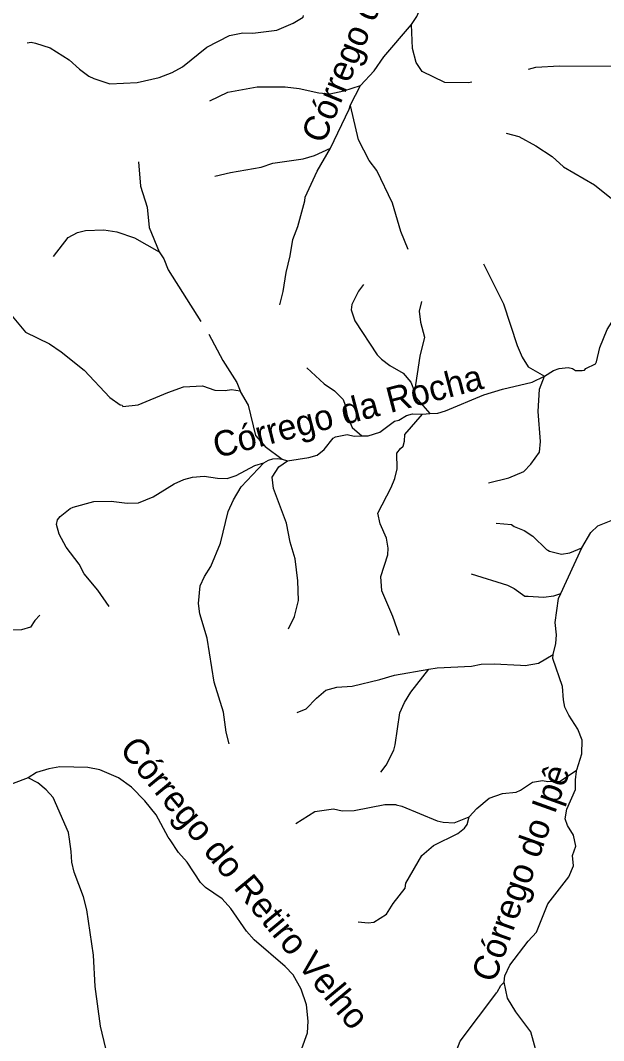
# Model space of a CAD drawing. Extents: x 393 to 446.6, y 8175.5 to 8231.
# Drawn here: x 437.39 to 441.07, y 8195.85 to 8202.28 of the extents above; entities that cross this region are included whole.
import ezdxf
from ezdxf.enums import TextEntityAlignment as Align

# ---------------------------------------------------------------- set-up
doc = ezdxf.new("R2010")
doc.units = 0
doc.header["$LTSCALE"] = 0.064
doc.linetypes.add('LONG_DASHED', pattern=[7.5, 6, -1.5])
doc.layers.add('61', color=7, linetype='Continuous')
doc.layers.add('7', color=7, linetype='Continuous', lineweight=25)
doc.layers.add('9', color=7, linetype='LONG_DASHED', lineweight=25)

msp = doc.modelspace()

# ---------------------------------------------------------------- linework, layer by layer
at = {"layer": '7'}
msp.add_lwpolyline([(440.601, 8201.9686), (440.6453, 8201.9814), (440.7959, 8201.9908), (441.1931, 8201.9875), (441.2706, 8201.9972), (441.3352, 8201.9908), (441.4224, 8201.9682), (441.4773, 8201.9536), (441.6582, 8201.881), (441.7421, 8201.8616), (441.8293, 8201.8616), (441.9424, 8201.8842), (442.0425, 8201.8955), (442.0828, 8201.8858), (442.0958, 8201.8745), (442.1168, 8201.8616), (442.1523, 8201.8551), (442.1878, 8201.8584), (442.2427, 8201.8761), (442.3235, 8201.9181), (442.3692, 8201.9452)], dxfattribs=at)
at = {"layer": '9'}
for p, q in [((439.9319, 8199.7953), (439.9768, 8199.7989)), ((439.0454, 8199.5117), (439.08, 8199.5009)), ((440.8033, 8198.6634), (440.9364, 8198.9526))]:
    msp.add_line(p, q, dxfattribs=at)
for points in [[(439.8622, 8202.2497), (439.8959, 8202.3014), (439.9141, 8202.3443), (439.9338, 8202.4352)], [(437.4373, 8202.1354), (437.4625, 8202.1389), (437.4894, 8202.1331), (437.5824, 8202.1038), (437.7019, 8202.0279), (437.7665, 8201.9698), (437.8262, 8201.9246), (437.8569, 8201.91), (437.9587, 8201.8762), (438.1315, 8201.8842), (438.2703, 8201.9165), (438.3527, 8201.9472), (438.4173, 8201.9827), (438.5707, 8202.107), (438.7144, 8202.1813), (438.7968, 8202.1975), (438.8597, 8202.1959), (439.0131, 8202.2152), (439.1149, 8202.2588), (439.1778, 8202.2976), (439.1804, 8202.3066)], [(439.5405, 8201.8656), (439.6254, 8201.9574), (439.6864, 8202.0472), (439.8622, 8202.2497)], [(440.2431, 8201.8865), (440.2213, 8201.8818), (440.0712, 8201.8859), (439.9287, 8201.954), (439.8919, 8202.0111), (439.8672, 8202.0982), (439.8622, 8202.2497)], [(438.5897, 8201.7686), (438.702, 8201.8234), (438.8885, 8201.8569), (439.064, 8201.8583), (439.1525, 8201.8464), (439.2766, 8201.8198), (439.3471, 8201.8139), (439.4348, 8201.8327), (439.5405, 8201.8656)], [(439.3506, 8201.4716), (439.4679, 8201.7171), (439.4759, 8201.7432), (439.5405, 8201.8656)], [(439.8417, 8200.8328), (439.7941, 8200.9464), (439.7421, 8201.1238), (439.642, 8201.33), (439.5951, 8201.3937), (439.5274, 8201.5227), (439.4765, 8201.7408), (439.4759, 8201.7432)], [(440.4592, 8201.5652), (440.5387, 8201.544), (440.647, 8201.4861), (440.7492, 8201.4188), (440.8209, 8201.3524), (441.0164, 8201.24), (441.1228, 8201.1534), (441.1525, 8201.1188), (441.195, 8201.043), (441.2443, 8200.8713), (441.2933, 8200.7752), (441.3225, 8200.7432), (441.3971, 8200.6977)], [(438.6202, 8201.2939), (438.7205, 8201.3176), (438.9133, 8201.3503), (438.9866, 8201.3767), (439.1791, 8201.4033), (439.2505, 8201.4241), (439.3506, 8201.4716)], [(439.03, 8200.4826), (439.053, 8200.5677), (439.0701, 8200.6874), (439.0968, 8200.7935), (439.1132, 8200.8953), (439.1437, 8200.9782), (439.1891, 8201.1398), (439.1908, 8201.1631), (439.2657, 8201.3252), (439.3506, 8201.4716)], [(438.1402, 8201.3847), (438.1509, 8201.2316), (438.1948, 8201.0989), (438.2056, 8200.9708), (438.2699, 8200.8168)], [(437.604, 8200.7874), (437.6954, 8200.9087), (437.7545, 8200.9395), (437.8049, 8200.9522), (437.9216, 8200.9556), (438.002, 8200.9438), (438.1148, 8200.9062), (438.2699, 8200.8168)], [(438.2699, 8200.8168), (438.2982, 8200.7744), (438.3273, 8200.7045), (438.5822, 8200.2995), (438.6708, 8200.1332), (438.7592, 8199.9939), (438.7802, 8199.9408)], [(440.3154, 8200.7411), (440.4421, 8200.4907), (440.5275, 8200.2264), (440.5601, 8200.1531), (440.5983, 8200.0926), (440.6999, 8200.0351)], [(440.6999, 8200.0351), (440.7587, 8200.0692), (440.7942, 8200.0821), (440.8508, 8200.0885), (440.8766, 8200.0821), (440.896, 8200.0692), (440.938, 8200.0692), (440.9541, 8200.0724), (440.9622, 8200.0821), (441.0219, 8200.1111), (441.03, 8200.1241), (441.051, 8200.2145), (441.0962, 8200.3292), (441.1253, 8200.3744), (441.1737, 8200.4196), (441.319, 8200.5181), (441.3416, 8200.5552), (441.3449, 8200.6053), (441.361, 8200.6699), (441.3971, 8200.6977)], [(439.5596, 8200.6119), (439.5265, 8200.5702), (439.4861, 8200.4867), (439.4817, 8200.4526), (439.5049, 8200.3836), (439.6455, 8200.1688), (439.6716, 8200.1405), (439.725, 8200.1011), (439.8082, 8200.0523), (439.8585, 8199.997), (439.88, 8199.9383), (439.88, 8199.9382)], [(437.2906, 8200.4762), (437.4256, 8200.3117), (437.5785, 8200.2372), (437.6521, 8200.188), (437.7955, 8200.0723), (437.9578, 8199.8989), (438.0244, 8199.8533), (438.0359, 8199.8522), (438.0414, 8199.8435), (438.1371, 8199.8525), (438.3252, 8199.9318), (438.4226, 8199.9659), (438.5433, 8199.9722), (438.6215, 8199.9449), (438.6859, 8199.9432), (438.7266, 8199.9497), (438.7802, 8199.9408)], [(439.9259, 8200.5041), (439.911, 8200.4428), (439.9185, 8200.3753), (439.9445, 8200.279), (439.9147, 8200.161), (439.88, 8199.9382)], [(439.2007, 8200.0875), (439.3113, 8199.9856), (439.3769, 8199.9424), (439.431, 8199.8866), (439.4439, 8199.8517), (439.4559, 8199.7842), (439.4883, 8199.7105), (439.5484, 8199.6577)], [(439.9768, 8199.7989), (440.0287, 8199.801), (440.0757, 8199.8156), (440.3179, 8199.9174), (440.4358, 8199.9529), (440.6231, 8199.9965), (440.6999, 8200.0351)], [(440.3471, 8199.3614), (440.4752, 8199.3929), (440.5696, 8199.4329), (440.6157, 8199.4803), (440.6688, 8199.5555), (440.6763, 8199.6213), (440.6602, 8199.8118), (440.6701, 8199.9518), (440.6999, 8200.0351)], [(438.7802, 8199.9408), (438.7814, 8199.9378), (438.8304, 8199.852), (438.8783, 8199.6609), (438.9379, 8199.5906), (439.0454, 8199.5117)], [(439.88, 8199.9382), (439.8797, 8199.9361), (439.8898, 8199.899), (439.9768, 8199.7989)], [(439.5484, 8199.6577), (439.5891, 8199.6581), (439.6616, 8199.6815), (439.7543, 8199.7494), (439.7808, 8199.7562), (439.8302, 8199.7866), (439.869, 8199.7963), (439.9319, 8199.7953)], [(439.7865, 8198.3993), (439.7445, 8198.5191), (439.6752, 8198.6806), (439.6688, 8198.7717), (439.7122, 8198.9088), (439.7138, 8198.9501), (439.7041, 8199.0131), (439.665, 8199.1031), (439.6497, 8199.1714), (439.7345, 8199.3321), (439.7574, 8199.3893), (439.7719, 8199.4493), (439.7702, 8199.5495), (439.7926, 8199.5792), (439.8091, 8199.5923), (439.8182, 8199.6238), (439.8188, 8199.6658), (439.9319, 8199.7953)], [(439.08, 8199.5009), (439.2134, 8199.5218), (439.2666, 8199.5363), (439.3102, 8199.5718), (439.3684, 8199.6429), (439.3812, 8199.651), (439.4556, 8199.6671), (439.5008, 8199.6558), (439.5484, 8199.6577)], [(438.9308, 8199.4879), (438.9598, 8199.5056), (438.9873, 8199.5121), (439.0136, 8199.5159), (439.0454, 8199.5117)], [(439.0852, 8198.4411), (439.124, 8198.5193), (439.1485, 8198.6206), (439.1454, 8198.7446), (439.1275, 8198.8822), (439.0952, 8198.9878), (439.0741, 8199.1076), (438.9908, 8199.3271), (438.9826, 8199.3968), (439.0241, 8199.4617), (439.08, 8199.5009)], [(437.9533, 8198.5831), (437.8827, 8198.6853), (437.7972, 8198.7887), (437.7649, 8198.8484), (437.6825, 8198.9566), (437.6389, 8199.0373), (437.6228, 8199.0987), (437.6292, 8199.1277), (437.6454, 8199.1488), (437.7084, 8199.2004), (437.7261, 8199.2085), (437.8569, 8199.244), (437.9667, 8199.2456), (438.0669, 8199.2327), (438.1395, 8199.236), (438.2316, 8199.2731), (438.364, 8199.3554), (438.4254, 8199.3829), (438.4803, 8199.3974), (438.5545, 8199.4039), (438.6385, 8199.391), (438.6982, 8199.3894), (438.7564, 8199.4087), (438.8726, 8199.4701), (438.9308, 8199.4879)], [(438.7103, 8197.7174), (438.6917, 8197.7907), (438.6755, 8197.9166), (438.6158, 8198.1046), (438.5734, 8198.3819), (438.5269, 8198.536), (438.5173, 8198.6013), (438.5288, 8198.7128), (438.5562, 8198.7712), (438.5964, 8198.8338), (438.6575, 8198.9818), (438.7056, 8199.1803), (438.7377, 8199.2551), (438.7872, 8199.3362), (438.9308, 8199.4879)], [(440.9364, 8198.9526), (440.9942, 8199.0481), (441.0374, 8199.0915), (441.1522, 8199.1371), (441.2195, 8199.1357), (441.2777, 8199.1242), (441.3997, 8199.0731), (441.4423, 8199.0747), (441.5113, 8199.0992), (441.5766, 8199.1934), (441.6064, 8199.2147), (441.6487, 8199.2297), (441.8362, 8199.2541), (441.9199, 8199.2788), (441.9613, 8199.3066)], [(440.3949, 8199.1068), (440.4934, 8199.0983), (440.5088, 8199.0865), (440.5725, 8199.0608), (440.6283, 8199.0255), (440.7144, 8198.9426), (440.7219, 8198.9382), (440.7331, 8198.9317), (440.809, 8198.9132), (440.8604, 8198.9196), (440.9364, 8198.9526)], [(440.2388, 8198.7887), (440.4669, 8198.7172), (440.5101, 8198.6963), (440.5763, 8198.648), (440.5981, 8198.6466), (440.6949, 8198.6402), (440.7593, 8198.6497), (440.8033, 8198.6634)], [(440.7547, 8198.2789), (440.7721, 8198.35), (440.7761, 8198.4047), (440.7684, 8198.4818), (440.7893, 8198.6329), (440.8033, 8198.6634)], [(437.5171, 8198.5286), (437.4851, 8198.4942), (437.4574, 8198.4512), (437.4009, 8198.4349), (437.344, 8198.4333), (437.2677, 8198.4201), (437.2115, 8198.3513), (437.0993, 8198.1897), (437.0499, 8198.164), (436.9406, 8198.1476), (436.9088, 8198.1351), (436.8544, 8198.1491)], [(439.9717, 8198.1877), (440.0232, 8198.1966), (440.2409, 8198.2073), (440.3016, 8198.2184), (440.3835, 8198.2218), (440.5493, 8198.2123), (440.578, 8198.2106), (440.6636, 8198.2251), (440.7547, 8198.2789)], [(440.9054, 8197.5528), (440.9358, 8197.6546), (440.9378, 8197.7399), (440.911, 8197.8087), (440.854, 8197.8967), (440.8301, 8197.9475), (440.82, 8197.9934), (440.815, 8198.0781), (440.7541, 8198.2538), (440.7547, 8198.2789)], [(439.1411, 8197.9144), (439.197, 8197.9382), (439.2621, 8198.005), (439.3221, 8198.0554), (439.3901, 8198.0746), (439.4876, 8198.081), (439.6629, 8198.1219), (439.755, 8198.1505), (439.9717, 8198.1877)], [(439.6682, 8197.5376), (439.7012, 8197.5825), (439.7496, 8197.6771), (439.7592, 8197.7112), (439.7889, 8197.9127), (439.8179, 8197.9777), (439.8565, 8198.0424), (439.9717, 8198.1877)], [(439.1424, 8195.72), (439.2054, 8195.8961), (439.21, 8195.9684), (439.1986, 8196.0724), (439.1666, 8196.1706), (439.1147, 8196.2614), (439.0641, 8196.3137), (438.8691, 8196.4814), (438.8201, 8196.5365), (438.7223, 8196.678), (438.6667, 8196.7402), (438.5622, 8196.8112), (438.5307, 8196.8422), (438.4462, 8196.9703), (438.3917, 8197.0329), (438.3391, 8197.111), (438.3272, 8197.1286), (438.2512, 8197.2685), (438.1796, 8197.3582), (438.0942, 8197.4434), (438.0134, 8197.5032), (437.8962, 8197.5529), (437.8189, 8197.5681), (437.644, 8197.5711), (437.5735, 8197.5599), (437.4958, 8197.5357), (437.4428, 8197.5016)], [(440.2262, 8197.2563), (440.2742, 8197.3091), (440.352, 8197.3745), (440.4366, 8197.4029), (440.5211, 8197.413), (440.5488, 8197.4251), (440.6251, 8197.476), (440.6883, 8197.4852), (440.7216, 8197.479), (440.8, 8197.4821), (440.9037, 8197.5517), (440.9054, 8197.5528)], [(440.4459, 8196.2141), (440.4516, 8196.2542), (440.4817, 8196.3214), (440.5988, 8196.4729), (440.6507, 8196.5302), (440.7212, 8196.7081), (440.8536, 8196.8782), (440.8843, 8196.9483), (440.8783, 8197.0135), (440.8986, 8197.0709), (440.8831, 8197.1419), (440.8465, 8197.202), (440.8316, 8197.2442), (440.8428, 8197.3051), (440.8972, 8197.4297), (440.896, 8197.4903), (440.903, 8197.5449), (440.9054, 8197.5528)], [(437.4428, 8197.5016), (437.3488, 8197.4678), (437.3144, 8197.4451), (437.2369, 8197.4128), (437.1723, 8197.3935), (437.1529, 8197.3918), (437.112, 8197.4012)], [(438.0349, 8195.2723), (438.015, 8195.358), (437.9925, 8195.5202), (437.9585, 8195.6963), (437.8986, 8195.9384), (437.8667, 8196.1881), (437.8553, 8196.3851), (437.8132, 8196.67), (437.7919, 8196.7532), (437.7324, 8196.9083), (437.7184, 8196.9715), (437.7148, 8197.0374), (437.7031, 8197.1158), (437.6968, 8197.1575), (437.6008, 8197.3784), (437.5574, 8197.4279), (437.5039, 8197.4704), (437.4428, 8197.5016)], [(439.131, 8197.2156), (439.2521, 8197.2899), (439.3687, 8197.3063), (439.4239, 8197.2949), (439.5001, 8197.2967), (439.6938, 8197.3353), (439.7628, 8197.3335), (439.764, 8197.3332), (439.7998, 8197.3242), (440.0239, 8197.232), (440.0619, 8197.2223), (440.1304, 8197.2193), (440.2262, 8197.2563)], [(439.5244, 8196.5958), (439.5873, 8196.5877), (439.6248, 8196.5919), (439.7033, 8196.6435), (439.7458, 8196.7104), (439.8214, 8196.8081), (439.8257, 8196.8381), (439.9264, 8197.0134), (440, 8197.0754), (440.1548, 8197.1514), (440.1959, 8197.1862), (440.2122, 8197.2085), (440.2262, 8197.2563)], [(439.7778, 8195.4231), (439.8121, 8195.4103), (439.8682, 8195.4105), (439.9251, 8195.4665), (440.0137, 8195.5168), (440.0557, 8195.5539), (440.0689, 8195.5792), (440.0885, 8195.6713), (440.1272, 8195.7335), (440.1693, 8195.8432), (440.4027, 8196.1527), (440.4257, 8196.1946), (440.4459, 8196.2141)], [(440.6547, 8195.7575), (440.6145, 8195.9018), (440.5203, 8196.0288), (440.4665, 8196.113), (440.4459, 8196.2141)]]:
    msp.add_lwpolyline(points, dxfattribs=at)

# ---------------------------------------------------------------- texts
at = {"layer": '61'}
for s, rotation, p in [('Córrego das Pedras', 67.49, (439.6753, 8202.3767)), ('Córrego da Rocha', 14.604, (439.4793, 8199.7369)), ('Córrego do Retiro Velho', 309.611, (438.7491, 8196.7908)), ('Córrego do Ipê', 70.389, (440.6258, 8196.8769))]:
    msp.add_text(s, height=0.16, rotation=rotation, dxfattribs=at).set_placement(p, align=Align.CENTER)

doc.saveas('drawing.dxf')
